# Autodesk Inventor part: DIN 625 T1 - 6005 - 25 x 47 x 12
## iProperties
Library Location: C:\Program Files\Autodesk\Inventor 6\content
Library: local
SubLibrary: DIN
Family: 249
Member: 170
Member Major Revision: 1
Member Minor Revision: 1
Comments: To add or edit properties for Autodesk Inventor files, use iProperties.
Created: 2004-09
Part Number: DIN 625 T1 - 6005 - 25 x 47 x 12
Vendor: Autodesk Inc.
Document SubType Name: Modeling
Designer: Laurent
Description: Roulement rainuré à billes
Standard: DIN 625 T1 6005 - 25 x 47 x 12
Density: 1 g/cm^3
Alert: To add or edit properties for Autodesk Inventor files, use iProperties.
Control State: 0
Master: False
Checked Out: False
Shininess: 64.0
Length Units: 11269
Angle Units: 11279
Time Units: 11290
Mass Units: 11283
Length Display Precision: 3
Angle Display Precision: 2
Compacted: True
Classification: un/spsc 31171504
Density: 0.0
Volumn: 0.0
Area: 0.0
PropertySet Name: Model Information
Author: Laurent
Revision Number: 1
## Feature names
1. Corps [Revolution]
2. Congé1 [Fillet]
3. Sphère [Revolution]
4. Sphères [Circular Pattern]
